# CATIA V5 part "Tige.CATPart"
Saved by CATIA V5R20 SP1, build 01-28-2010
Part number: Tige
Bounding box of the stored display mesh (mm): x -4 to 140, y -20 to 24.694, z -4 to 4
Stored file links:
  F:\Pro\Emplois\1_Chercheur\ThinkMOTION\MMS\MMS_GR1\abruchon\Catia\Tige.CATPart
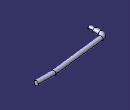
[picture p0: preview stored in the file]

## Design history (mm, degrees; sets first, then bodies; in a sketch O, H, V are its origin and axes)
Set1
  Plane1: type Normal, Curve Sketch1, RefPoint Sketch1.P2
  Plane2: type Normal, Curve Sketch1, RefPoint Sketch1.P3
  Sweep1: type Unspec, Profile Sketch2, Guide Sketch1
Body1 (main body)
  Sketch1 on xy-plane, origin (0, 0, 0), H (1, 0, 0), V (0, 1, 0)
    line L1 (8.0025, 9) -> (107.3164, 20.6936)
    point P2 (107.3164, 20.6936)
    line L2 (0, 0) -> (0, -20)
    point P3 (0, -20)
    arc A1 centre (9.0622, 0) radius 9.0622 from (0, 0) to (8.0025, 9) cw
    line L3 (107.3164, 20.6936) -> (140, 20.6936)
    distance L2 A1 = 0
    length L1 = 100
    vertical: L2 V
    tangency: A1 L1
    horizontal: L3 H
  Sketch2 on zx-plane, origin (0, 0, 0), H (-1, 0, 0), V (0, 0, 1)
    circle A1 centre (0, 0) radius 4
    radius A1 = 4
  CloseSurface1: CloseElement Sweep1
  Sketch3 on face of CloseSurface1, origin (0, -20, 0), H (1, 0, 0), V (0, 0, 1)
    circle A1 centre (0, 0) radius 3
  Pocket1: profile Sketch3, direction (0, 1, 0), length 10, outer side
